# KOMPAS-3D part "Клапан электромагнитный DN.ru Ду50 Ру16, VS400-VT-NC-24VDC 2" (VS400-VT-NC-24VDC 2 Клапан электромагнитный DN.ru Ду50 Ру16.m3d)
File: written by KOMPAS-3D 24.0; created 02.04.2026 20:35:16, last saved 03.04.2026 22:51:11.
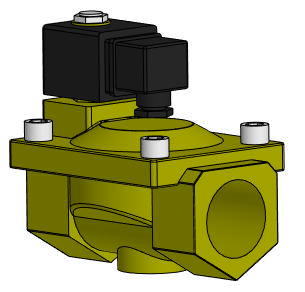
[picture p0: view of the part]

Document properties: Автор: artio; Полное имя файла: C:\Users\artio\OneDrive\Рабочий стол\Клапан электромагнитный DN.ru\VS400-VT-NC\VS400-VT-NC-24VDC 2 Клапан электромагнитный DN.ru Ду50 Ру16.m3d

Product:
- Body: Тело 1  | qty 1
    Масса: 7.119215
- Part/product: Клапан электромагнитный DN.ru Ду50 Ру16  | designation VS400-VT-NC-24VDC 2
    Масса: 3.509
    Раздел спецификации: Прочие изделия
    Примечание: D130-04738
    additional columns: ef56311e-7521-43dc-8291-0e6108b3d81d; VS400-ET-NC-220VAC 2; artio; c; Шероховатость не задана; Да

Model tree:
1. Операция без истории:1

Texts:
  VS400-VT-NC-24VDC 2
